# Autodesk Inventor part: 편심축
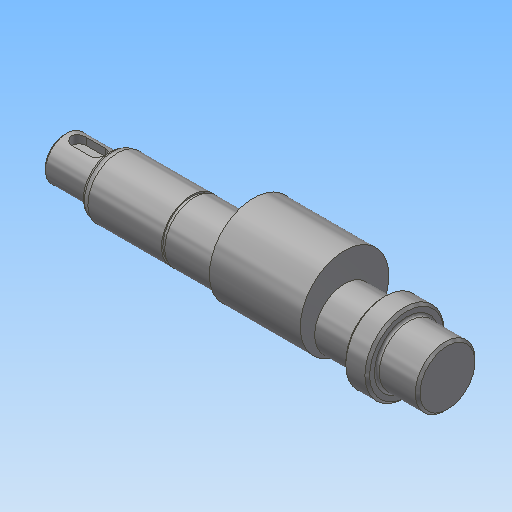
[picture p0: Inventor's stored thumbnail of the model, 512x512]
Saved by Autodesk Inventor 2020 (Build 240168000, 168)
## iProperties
Created: 2023-03
Part Number: 편심축
Material: 강철, 연강
Document SubType Name: Modeling
Designer: mdu-01
Density: 1 g/cm^3
Appearance: 강철
Author: mdu-01
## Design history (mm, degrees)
sketch "스케치1"
  geometry: L1 (0, 0)-(160, 0); L2 (160, 0)-(160, 11.5); L3 (159, 12.5)-(144, 12.5); L4 (143, 13.5)-(143, 16.5); L5 (143, 16.5)-(133, 16.5); L6 (133, 16.5)-(133, 12.5); L7 (19, 10.961)-(19, 9); L8 (19, 9)-(1, 9); L9 (0, 8)-(0, 0); L10 (79, 12.5)-(79, 0); L11 (117, 12.5)-(117, 0); L12 (160, 11.5)-(159, 12.5); L13 (54.35, 12.5)-(54.35, 11.95); L14 (54.35, 11.95)-(53, 11.95); L15 (53, 11.95)-(53, 12.5); L16 (133, 12.5)-(54.35, 12.5); L17 (53, 12.5)-(22.237, 12.5); L18 (19.25, 11.394)-(20.237, 11.964); L19 (1, 9)-(0, 8); L20 (3, 5.5)-(17, 5.5); L21 (3, 5.5)-(3, 9); L22 (17, 5.5)-(17, 9); A1 r 1 centre (144, 13.5) between (143, 13.5) and (144, 12.5); A2 r 0.5 centre (19.5, 10.961) between (19.25, 11.394) and (19, 10.961); A3 r 4 centre (22.237, 8.5) between (22.237, 12.5) and (20.237, 11.964); 3 further points
  constraints: 44 end point, 12 perpendicular, 12 point on line, 10 parallel, 6 point on circle, 6 tangent, 3 centre point, 2 collinear, 1 horizontal
  dimensions: "d0" = 18 diameter of L8 L1; "d2" = 38 distance between parallel lines of L11 L10; "d3" = 16 distance between parallel lines of L6 L11; "d4" = 25 diameter of L3 L1; "d5" = 17 distance between parallel lines of L2 L4; "d6" = 1 distance of L2.end point (160, 12.5); "d7" = 1 distance of L3.start point (160, 12.5) (= d6); "d8" = 10 distance between parallel lines of L4 L6; "d9" = 33 diameter of L5 L1; "d10" = 1 radius of A1; "d11" = 23.9 diameter of L14 L1; "d12" = 1.35 distance between parallel lines of L13 L15; "d13" = 26 distance between parallel lines of L15 L10; "d14" = 34 distance between parallel lines of L7 L15; "d15" = 19 distance between parallel lines of L9 L7; "d16" = 22.5 diameter of point (19, 11.25) L1; "d17" = 30 deg angle of L18 L17; "d18" = 0.5 radius of A2; "d19" = 1.96132 distance of L7.start L7.end (derived); "d20" = 4 radius of A3; "d21" = 1 distance of L8.end point (0, 9); "d22" = 1 distance of L9.start point (0, 9) (= d21); "d24" = 3.5 distance between parallel lines of L20 L8; "d25" = 14 distance between parallel lines of L22 L21; "d26" = 2 distance between parallel lines of L7 L22; "d45" = 160 distance between parallel lines of L2 L9 (derived)
revolve "회전1" stored, may be unused: angle "d23" = 90 deg
extrude "돌출1" cut sketch "스케치1" stored distance "d27" = 6; taper "d28" = 0 deg
fillet "모깎기1"
fillet "모깎기2"
hole "구멍1" diameter "d31" = 6.647; stored, may be unused: countersink angle "d35" = 90 deg, drill point angle "d37" = 118 deg; dims "d32" = 16, "d33" = 4, "d34" = 2, "d36" = 18, "d48" = 10, "d49" = 10
sketch "스케치2"
  geometry: L1 (79, 6)-(117, 6); L2 (117, 12.5)-(117, 0) reference; L3 (79, 12.5)-(79, 0) reference; L4 (79, 6)-(79, -12.5); L5 (79, -12.5)-(117, -12.5); L6 (117, -12.5)-(117, 6); 1 further point
  constraints: 8 end point, 3 perpendicular, 2 collinear, 2 point on line, 1 horizontal
  dimensions: "d39" = 6 distance from line of point (0, 0) L1; "d40" = 12.5 distance from line of L5 point (0, 0)
revolve "회전2" sketch "스케치2" stored, may be unused: angle "d41" = 90 deg
chamfer "모따기1" distance "d42" = 1; stored, may be unused: second distance "d43" = 2, angle "d44" = 45 deg
node "솔리드1"
